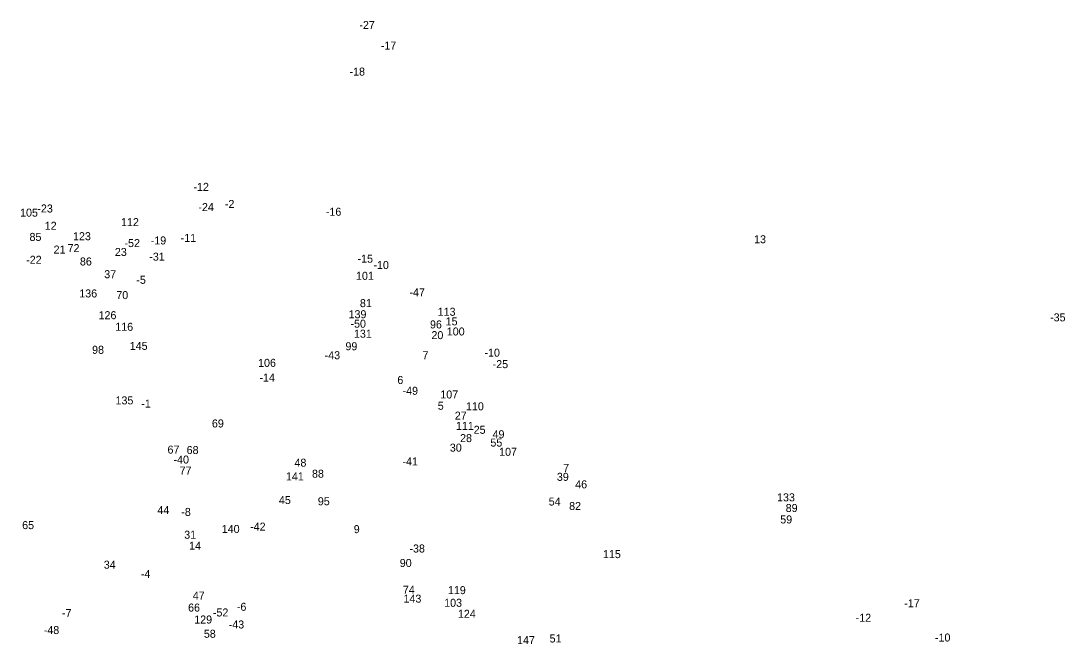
# Model space of a CAD drawing. Extents: x -790709 to -785360, y -974907 to -970918.
# Drawn here: x -788601 to -787295, y -973722 to -972943 of the extents above; entities that cross this region are included whole.
import ezdxf

# ---------------------------------------------------------------- set-up
doc = ezdxf.new("R2010")
doc.units = 0
doc.layers.add('Vrstva 15', color=7, linetype='Continuous')
doc.layers.add('Vrstva 63', color=7, linetype='Continuous')

msp = doc.modelspace()

# ---------------------------------------------------------------- texts
at = {"layer": 'Vrstva 15'}
for s, p in [('-27', (-788177.6, -972953.5)), ('-17', (-788150.8, -972979.2)), ('-18', (-788189.9, -973011.7)), ('-12', (-788385, -973155.7)), ('-23', (-788580.1, -973182.7)), ('-24', (-788378.8, -973180.9)), ('-2', (-788345.7, -973177.1)), ('-16', (-788219.5, -973186.8)), ('-19', (-788438.4, -973222.6)), ('-11', (-788401, -973219.5)), ('-52', (-788471.2, -973225.9)), ('-22', (-788594.1, -973246.8)), ('-31', (-788440.2, -973242.9)), ('-15', (-788179.9, -973245.4)), ('-10', (-788160, -973253.3)), ('-5', (-788456.4, -973271.8)), ('-47', (-788115, -973287.4)), ('-50', (-788188.7, -973326.6)), ('-35', (-787314.2, -973318.7)), ('-43', (-788221, -973366)), ('-10', (-788021.2, -973362.8)), ('-25', (-788011, -973377.1)), ('-14', (-788302.5, -973393.9)), ('-49', (-788123.6, -973410.4)), ('-1', (-788450.2, -973426.3)), ('-40', (-788409.9, -973496.3)), ('-41', (-788123.7, -973498.6)), ('-8', (-788400.2, -973561.7)), ('-42', (-788314.2, -973580.1)), ('-38', (-788115, -973607.4)), ('-4', (-788450.7, -973639.2)), ('-6', (-788330.7, -973680.2)), ('-17', (-787496.5, -973675.8)), ('-7', (-788549.3, -973688)), ('-52', (-788360.7, -973687.3)), ('-12', (-787557.2, -973693.9)), ('-43', (-788340.9, -973702.3)), ('-48', (-788572.1, -973709.3)), ('-10', (-787458.1, -973718.6))]:
    msp.add_text(s, height=10, dxfattribs=at).set_placement(p)
at = {"layer": 'Vrstva 63'}
for s, p in [('105', (-788601.7, -973187.9)), ('12', (-788570.9, -973204.3)), ('112', (-788475.5, -973199.7)), ('85', (-788589.9, -973218.2)), ('123', (-788535.5, -973217.3)), ('13', (-787684.2, -973221.1)), ('21', (-788559.8, -973234)), ('72', (-788542.3, -973232.2)), ('23', (-788483.2, -973237)), ('86', (-788526.9, -973248.9)), ('37', (-788496.5, -973264.8)), ('101', (-788181.8, -973266.8)), ('136', (-788527.7, -973288.8)), ('70', (-788481.4, -973290.9)), ('81', (-788176.9, -973300.9)), ('126', (-788503.6, -973316)), ('139', (-788191.1, -973314.8)), ('113', (-788079.7, -973311.7)), ('96', (-788089.3, -973327.5)), ('15', (-788069.7, -973323.7)), ('116', (-788482.7, -973330.5)), ('131', (-788184.4, -973339.1)), ('20', (-788087.5, -973340.9)), ('100', (-788068.3, -973336.3)), ('145', (-788464.6, -973354.3)), ('99', (-788195, -973354.8)), (' 98', (-788515.4, -973359.2)), ('7', (-788098.7, -973366)), ('106', (-788304.2, -973375.5)), ('6', (-788130.1, -973396.9)), ('107', (-788076.4, -973415)), ('135', (-788482.4, -973422.4)), ('5', (-788079.6, -973429.1)), ('110', (-788044.3, -973429.8)), ('27', (-788058.3, -973441.4)), ('69', (-788361.9, -973451.2)), ('111', (-788056.9, -973454.2)), ('25', (-788034.7, -973459.1)), ('28', (-788051.7, -973469.5)), ('49', (-788011.1, -973464.7)), ('67', (-788417.4, -973483.9)), ('68', (-788393.5, -973484.4)), ('30', (-788064.5, -973481.4)), ('55', (-788013.8, -973475.1)), ('107', (-788002.9, -973486.6)), ('77', (-788402.3, -973510.1)), ('48', (-788258.7, -973500.2)), ('7', (-787922.8, -973506.7)), ('141', (-788269.4, -973517.3)), ('88', (-788236.8, -973514)), ('39', (-787930.7, -973517.9)), ('46', (-787907.8, -973527.3)), ('45', (-788278.2, -973546.9)), ('95', (-788229.5, -973548.4)), ('54', (-787940.9, -973548.7)), ('133', (-787655.5, -973543.5)), ('44', (-788430, -973559.3)), ('82', (-787915.4, -973554.3)), ('89', (-787644.7, -973556.8)), ('59', (-787651.5, -973571.1)), ('65', (-788599.1, -973578.2)), ('31', (-788396.5, -973590.2)), ('140', (-788349.6, -973583)), ('9', (-788184.6, -973583.2)), ('14', (-788390.4, -973603.9)), ('115', (-787873.1, -973614.4)), ('34', (-788497.1, -973627.6)), ('90', (-788127.1, -973625.5)), ('47', (-788385.8, -973666.2)), (' 74', (-788126.9, -973658.9)), ('119', (-788066.9, -973659.4)), ('66', (-788391.7, -973681.2)), ('143', (-788122.4, -973670)), ('103', (-788071.6, -973675.2)), ('124', (-788054.4, -973689)), ('129', (-788384, -973696.1)), ('58', (-788372, -973713.9)), ('51', (-787939.8, -973719.8)), ('147', (-787980.5, -973721.8))]:
    msp.add_text(s, height=10, dxfattribs=at).set_placement(p)

doc.saveas('drawing.dxf')
